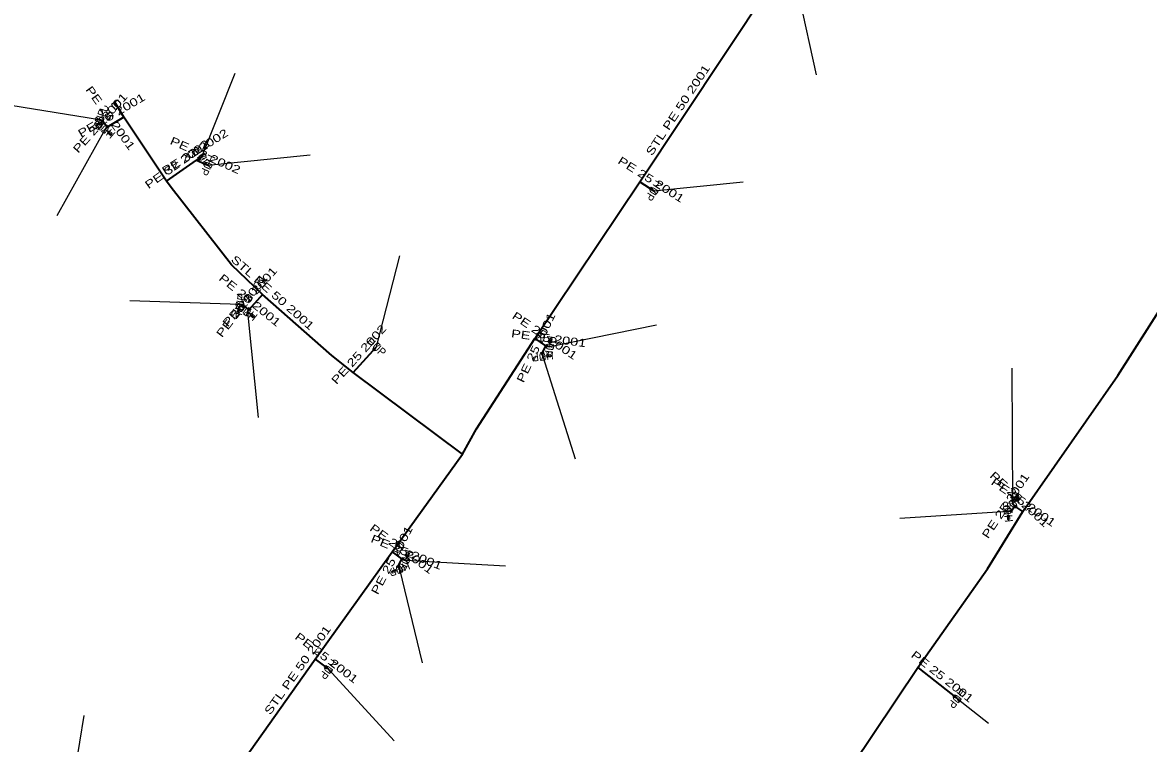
# Model space of a CAD drawing. Extents: x -737484 to -734496, y -1033882 to -1030666.
# Drawn here: x -734902.5 to -734761.8, y -1033507.1 to -1033417 of the extents above; entities that cross this region are included whole.
import ezdxf
from ezdxf.enums import TextEntityAlignment as Align

# ---------------------------------------------------------------- set-up
doc = ezdxf.new("R2010")
doc.units = 0
doc.header["$LTSCALE"] = 0.4
for name, color, linetype, lineweight in [('1', 7, 'Continuous', 13), ('22', 7, 'Continuous', 25), ('5', 7, 'Continuous', 35), ('7', 7, 'Continuous', 35)]:
    doc.layers.add(name, color=color, linetype=linetype, lineweight=lineweight)
doc.layers.add('2', color=7, linetype='Continuous')

msp = doc.modelspace()

# ---------------------------------------------------------------- linework, layer by layer
at = {"layer": '1'}
for p, q in [((-734892.85, -1033429.17), (-734893.012, -1033429.642)), ((-734893.108, -1033429.689), (-734893.222, -1033430.02)), ((-734892.14, -1033430.34), (-734891.762, -1033430.668)), ((-734891.755, -1033430.773), (-734891.491, -1033431.003)), ((-734875.493, -1033452.79), (-734875.56, -1033453.133)), ((-734875.31, -1033452.24), (-734875.405, -1033452.73)), ((-734874.39, -1033453.15), (-734873.995, -1033453.457)), ((-734873.983, -1033453.563), (-734873.707, -1033453.778)), ((-734836.62, -1033457.48), (-734836.55, -1033456.984)), ((-734836.465, -1033456.921), (-734836.416, -1033456.574)), ((-734837.5, -1033458.72), (-734837.002, -1033458.667)), ((-734836.92, -1033458.734), (-734836.572, -1033458.697)), ((-734778.76, -1033477.18), (-734778.473, -1033476.77)), ((-734778.368, -1033476.752), (-734778.168, -1033476.465)), ((-734779.4, -1033478.09), (-734779.347, -1033478.587)), ((-734779.414, -1033478.669), (-734779.377, -1033479.017)), ((-734854.65, -1033484.19), (-734854.462, -1033483.726)), ((-734854.365, -1033483.684), (-734854.233, -1033483.36)), ((-734855.951, -1033485.435), (-734856.275, -1033485.566)), ((-734855.39, -1033485.29), (-734855.853, -1033485.477))]:
    msp.add_line(p, q, dxfattribs=at)
msp.add_lwpolyline([(-734891.249, -1033427.421), (-734891.378, -1033427.207), (-734890.521, -1033426.692), (-734890.392, -1033426.906)], dxfattribs=at)
for points in [[(-734893.386, -1033429.195), (-734893.256, -1033428.817), (-734892.441, -1033429.52), (-734892.311, -1033429.142)], [(-734893.175, -1033430.115), (-734893.317, -1033430.066), (-734893.154, -1033429.593), (-734893.012, -1033429.642)], [(-734893.198, -1033430.067), (-734893.269, -1033430.043), (-734893.13, -1033429.641), (-734893.059, -1033429.665)], [(-734893.175, -1033430.115), (-734893.033, -1033430.164), (-734892.87, -1033429.691), (-734893.012, -1033429.642)], [(-734892.316, -1033430.847), (-734892.617, -1033430.585), (-734891.66, -1033430.092), (-734891.961, -1033429.83)], [(-734891.385, -1033430.996), (-734891.483, -1033431.109), (-734891.861, -1033430.781), (-734891.762, -1033430.668)], [(-734891.438, -1033430.999), (-734891.487, -1033431.055), (-734891.808, -1033430.776), (-734891.758, -1033430.72)], [(-734891.385, -1033430.996), (-734891.286, -1033430.882), (-734891.664, -1033430.554), (-734891.762, -1033430.668)], [(-734879.75, -1033433.355), (-734879.538, -1033433.694), (-734880.599, -1033433.885), (-734880.387, -1033434.224)], [(-734878.801, -1033434.85), (-734878.964, -1033435.216), (-734879.715, -1033434.443), (-734879.878, -1033434.809)], [(-734823.099, -1033438.114), (-734823.311, -1033438.453), (-734823.948, -1033437.584), (-734824.16, -1033437.923)], [(-734875.837, -1033452.339), (-734875.761, -1033451.947), (-734874.856, -1033452.53), (-734874.78, -1033452.138)], [(-734875.5, -1033453.221), (-734875.648, -1033453.193), (-734875.552, -1033452.702), (-734875.405, -1033452.73)], [(-734875.529, -1033453.177), (-734875.603, -1033453.162), (-734875.522, -1033452.745), (-734875.448, -1033452.76)], [(-734875.5, -1033453.221), (-734875.353, -1033453.25), (-734875.258, -1033452.759), (-734875.405, -1033452.73)], [(-734874.54, -1033453.666), (-734874.855, -1033453.419), (-734873.924, -1033452.878), (-734874.239, -1033452.631)], [(-734873.601, -1033453.765), (-734873.694, -1033453.883), (-734874.088, -1033453.576), (-734873.995, -1033453.457)], [(-734873.654, -1033453.771), (-734873.7, -1033453.83), (-734874.035, -1033453.568), (-734873.989, -1033453.509)], [(-734873.601, -1033453.765), (-734873.509, -1033453.647), (-734873.903, -1033453.339), (-734873.995, -1033453.457)], [(-734858.084, -1033457.023), (-734857.786, -1033457.291), (-734858.753, -1033457.766), (-734858.455, -1033458.034)], [(-734836.097, -1033457.351), (-734836.152, -1033457.747), (-734837.087, -1033457.212), (-734837.142, -1033457.608)], [(-734836.48, -1033456.489), (-734836.629, -1033456.468), (-734836.698, -1033456.963), (-734836.55, -1033456.984)], [(-734836.48, -1033456.489), (-734836.332, -1033456.51), (-734836.401, -1033457.005), (-734836.55, -1033456.984)], [(-734836.449, -1033456.532), (-734836.375, -1033456.542), (-734836.434, -1033456.963), (-734836.508, -1033456.953)], [(-734837.239, -1033459.19), (-734837.636, -1033459.239), (-734837.361, -1033458.198), (-734837.758, -1033458.247)], [(-734836.505, -1033458.615), (-734836.521, -1033458.466), (-734837.018, -1033458.518), (-734837.002, -1033458.667)], [(-734836.505, -1033458.615), (-734836.489, -1033458.764), (-734836.987, -1033458.816), (-734837.002, -1033458.667)], [(-734836.539, -1033458.656), (-734836.531, -1033458.73), (-734836.954, -1033458.775), (-734836.962, -1033458.7)], [(-734779.261, -1033476.984), (-734778.988, -1033476.691), (-734778.529, -1033477.666), (-734778.256, -1033477.373)], [(-734778.186, -1033476.36), (-734778.309, -1033476.274), (-734778.596, -1033476.684), (-734778.473, -1033476.77)], [(-734778.186, -1033476.36), (-734778.063, -1033476.446), (-734778.35, -1033476.856), (-734778.473, -1033476.77)], [(-734778.177, -1033476.413), (-734778.116, -1033476.456), (-734778.36, -1033476.804), (-734778.421, -1033476.761)], [(-734779.875, -1033478.34), (-734779.917, -1033477.942), (-734778.88, -1033478.235), (-734778.922, -1033477.837)], [(-734779.295, -1033479.084), (-734779.444, -1033479.1), (-734779.496, -1033478.602), (-734779.347, -1033478.587)], [(-734779.336, -1033479.05), (-734779.41, -1033479.058), (-734779.455, -1033478.635), (-734779.38, -1033478.627)], [(-734779.295, -1033479.084), (-734779.146, -1033479.068), (-734779.198, -1033478.571), (-734779.347, -1033478.587)], [(-734854.11, -1033484.191), (-734854.26, -1033484.562), (-734855.037, -1033483.817), (-734855.187, -1033484.188)], [(-734854.275, -1033483.262), (-734854.414, -1033483.206), (-734854.601, -1033483.67), (-734854.462, -1033483.726)], [(-734854.275, -1033483.262), (-734854.136, -1033483.319), (-734854.323, -1033483.782), (-734854.462, -1033483.726)], [(-734854.255, -1033483.311), (-734854.185, -1033483.34), (-734854.344, -1033483.734), (-734854.414, -1033483.705)], [(-734856.317, -1033485.664), (-734856.373, -1033485.525), (-734855.909, -1033485.338), (-734855.853, -1033485.477)], [(-734856.295, -1033485.616), (-734856.323, -1033485.546), (-734855.929, -1033485.387), (-734855.901, -1033485.456)], [(-734856.317, -1033485.664), (-734856.26, -1033485.803), (-734855.797, -1033485.616), (-734855.853, -1033485.477)], [(-734855.016, -1033485.678), (-734855.387, -1033485.828), (-734855.39, -1033484.751), (-734855.761, -1033484.901)], [(-734863.75, -1033497.941), (-734863.991, -1033498.26), (-734864.548, -1033497.339), (-734864.789, -1033497.658)], [(-734785.231, -1033501.59), (-734785.478, -1033501.905), (-734786.019, -1033500.974), (-734786.266, -1033501.289)]]:
    msp.add_lwpolyline(points, close=True, dxfattribs=at)
at = {"layer": '22'}
for p, q in [((-734805.939, -1033411.689), (-734803.327, -1033423.565)), ((-734880.069, -1033433.79), (-734875.902, -1033423.352)), ((-734892.849, -1033429.169), (-734903.914, -1033427.384)), ((-734892.139, -1033430.339), (-734898.184, -1033441.178)), ((-734879.34, -1033434.83), (-734866.565, -1033433.538)), ((-734823.63, -1033438.019), (-734812.452, -1033436.934)), ((-734858.27, -1033457.529), (-734855.34, -1033446.166)), ((-734875.309, -1033452.239), (-734889.059, -1033451.788)), ((-734874.39, -1033453.149), (-734873.057, -1033466.331)), ((-734836.62, -1033457.48), (-734823.274, -1033454.759)), ((-734837.499, -1033458.719), (-734833.46, -1033471.524)), ((-734778.759, -1033477.179), (-734778.873, -1033460.195)), ((-734779.399, -1033478.089), (-734792.909, -1033478.977)), ((-734854.649, -1033484.19), (-734842.161, -1033484.893)), ((-734855.389, -1033485.29), (-734852.559, -1033496.989)), ((-734864.27, -1033497.8), (-734856.071, -1033506.748)), ((-734785.749, -1033501.44), (-734781.826, -1033504.54)), ((-734896.799, -1033516.13), (-734894.789, -1033503.567))]:
    msp.add_line(p, q, dxfattribs=at)
at = {"layer": '5'}
for points in [[(-734847.5, -1033470.91), (-734845.75, -1033467.75), (-734838.48, -1033456.5), (-734825.36, -1033436.93), (-734809.35, -1033412.75), (-734806.63, -1033409.56), (-734795.41, -1033392.89), (-734791.45, -1033386.95), (-734791.32, -1033386.62)], [(-734906.09, -1033665.06), (-734888.5, -1033639.81), (-734880.72, -1033628.44), (-734878.34, -1033625.02), (-734861.29, -1033600.17), (-734846.09, -1033578.13), (-734833.74, -1033559.94), (-734831.24, -1033556.38), (-734822.28, -1033543.88), (-734807.45, -1033522.2), (-734804.35, -1033518.03), (-734790.66, -1033497.56), (-734781.96, -1033485.26), (-734777.54, -1033478.09), (-734765.66, -1033461.1), (-734757.47, -1033448.23), (-734746.38, -1033431.46), (-734738.04, -1033419.32), (-734736.48, -1033416), (-734735.83, -1033412.08), (-734737.89, -1033406.38), (-734742.16, -1033400.46), (-734751.3, -1033390.22), (-734751.59, -1033389.68)], [(-734847.5, -1033470.91), (-734861.18, -1033460.75), (-734863.83, -1033458.62), (-734872.49, -1033450.98), (-734876.39, -1033447.3), (-734883.92, -1033437.63), (-734884.47, -1033436.85), (-734889.8, -1033428.84), (-734890.95, -1033426.95)], [(-734886.84, -1033526.23), (-734886.54, -1033525.7), (-734879.09, -1033515.1), (-734865.93, -1033496.54), (-734856.29, -1033483.14), (-734847.5, -1033470.91)]]:
    msp.add_lwpolyline(points, dxfattribs=at)
at = {"layer": '7'}
for p, q in [((-734889.8, -1033428.84), (-734891.91, -1033430.08)), ((-734891.91, -1033430.08), (-734892.139, -1033430.339)), ((-734884.47, -1033436.85), (-734880.74, -1033434.21)), ((-734880.74, -1033434.21), (-734880.069, -1033433.79)), ((-734880.74, -1033434.21), (-734879.34, -1033434.83)), ((-734825.36, -1033436.93), (-734823.63, -1033438.019)), ((-734872.49, -1033450.98), (-734874.19, -1033452.89)), ((-734874.19, -1033452.89), (-734874.39, -1033453.149)), ((-734861.18, -1033460.75), (-734858.27, -1033457.529)), ((-734838.48, -1033456.5), (-734837.14, -1033457.41)), ((-734837.14, -1033457.41), (-734836.62, -1033457.48)), ((-734778.51, -1033477.41), (-734778.759, -1033477.179)), ((-734777.54, -1033478.09), (-734778.51, -1033477.41)), ((-734865.93, -1033496.54), (-734864.27, -1033497.8)), ((-734790.66, -1033497.56), (-734785.749, -1033501.44))]:
    msp.add_line(p, q, dxfattribs=at)
for points in [[(-734891.91, -1033430.08), (-734892.47, -1033429.3), (-734892.849, -1033429.169)], [(-734874.19, -1033452.89), (-734874.89, -1033452.32), (-734875.309, -1033452.239)], [(-734837.14, -1033457.41), (-734837.55, -1033458.28), (-734837.499, -1033458.719)], [(-734778.51, -1033477.41), (-734778.93, -1033478.04), (-734779.399, -1033478.089)], [(-734856.29, -1033483.14), (-734855.12, -1033484), (-734854.649, -1033484.19)], [(-734855.12, -1033484), (-734855.57, -1033484.85), (-734855.389, -1033485.29)]]:
    msp.add_lwpolyline(points, dxfattribs=at)

# ---------------------------------------------------------------- texts
at = {"layer": '2', "width": 0.95}
for rotation, p in [(71, (-734892.376, -1033429.3313)), (139, (-734891.8105, -1033429.9614)), (302, (-734880.4927, -1033434.0545)), (246, (-734879.7967, -1033434.6261)), (238, (-734824.0533, -1033437.7535)), (79, (-734874.8179, -1033452.3339)), (142, (-734874.0817, -1033452.754)), (318, (-734858.6041, -1033457.8997)), (262, (-734837.1147, -1033457.4099)), (187, (-734837.5596, -1033458.2227)), (96, (-734778.9017, -1033478.0368)), (47, (-734778.393, -1033477.5195)), (248, (-734855.112, -1033484.0022)), (202, (-734855.5762, -1033484.826)), (233, (-734864.6685, -1033497.4986)), (232, (-734786.143, -1033501.1317))]:
    msp.add_text('HUP', height=1, rotation=rotation, dxfattribs=at).set_placement(p, align=Align.CENTER)
at = {"layer": '5', "width": 1.35}
for rotation, p in [(56.491, (-734820.1968, -1033428.227)), (318.581, (-734871.5653, -1033451.1279)), (54.661, (-734867.7105, -1033498.1872))]:
    msp.add_text('STL PE 50 2001', height=1, rotation=rotation, dxfattribs=at).set_placement(p, align=Align.CENTER)
at = {"layer": '7', "width": 1.35}
for s, rotation, p in [('PE 25 2001', 305.676, (-734891.9006, -1033429.2349)), ('PE 25 2001', 48.518, (-734892.399, -1033429.8777)), ('PE 25 2001', 30.442, (-734891.1078, -1033429.0284)), ('PE 32 2002', 32.044, (-734880.6688, -1033433.5756)), ('PE 32 2002', 35.29, (-734882.8929, -1033435.1215)), ('PE 32 2002', 336.114, (-734879.837, -1033434.0623)), ('PE 25 2001', 327.81, (-734824.2279, -1033437.0503)), ('PE 25 2001', 52.325, (-734874.6854, -1033452.7131)), ('PE 25 2001', 320.845, (-734874.3892, -1033452.0817)), ('PE 25 2001', 48.329, (-734873.7133, -1033451.6019)), ('PE 25 2001', 325.819, (-734837.5284, -1033456.5406)), ('PE 25 2001', 64.767, (-734837.8917, -1033457.8311)), ('PE 25 2002', 47.904, (-734860.096, -1033458.8042)), ('PE 25 2001', 352.333, (-734836.8127, -1033456.9492)), ('PE 25 2001', 56.31, (-734779.2659, -1033477.6428)), ('PE 25 2001', 317.148, (-734778.2936, -1033476.9275)), ('PE 25 2001', 324.968, (-734777.7375, -1033477.34)), ('PE 25 2001', 323.683, (-734855.4081, -1033483.1661)), ('PE 25 2001', 338.031, (-734854.6971, -1033483.6304)), ('PE 25 2001', 62.103, (-734855.8974, -1033484.4009)), ('PE 25 2001', 322.8, (-734864.7973, -1033496.7715)), ('PE 25 2001', 321.689, (-734787.894, -1033499.1071))]:
    msp.add_text(s, height=1, rotation=rotation, dxfattribs=at).set_placement(p, align=Align.CENTER)

doc.saveas('drawing.dxf')
